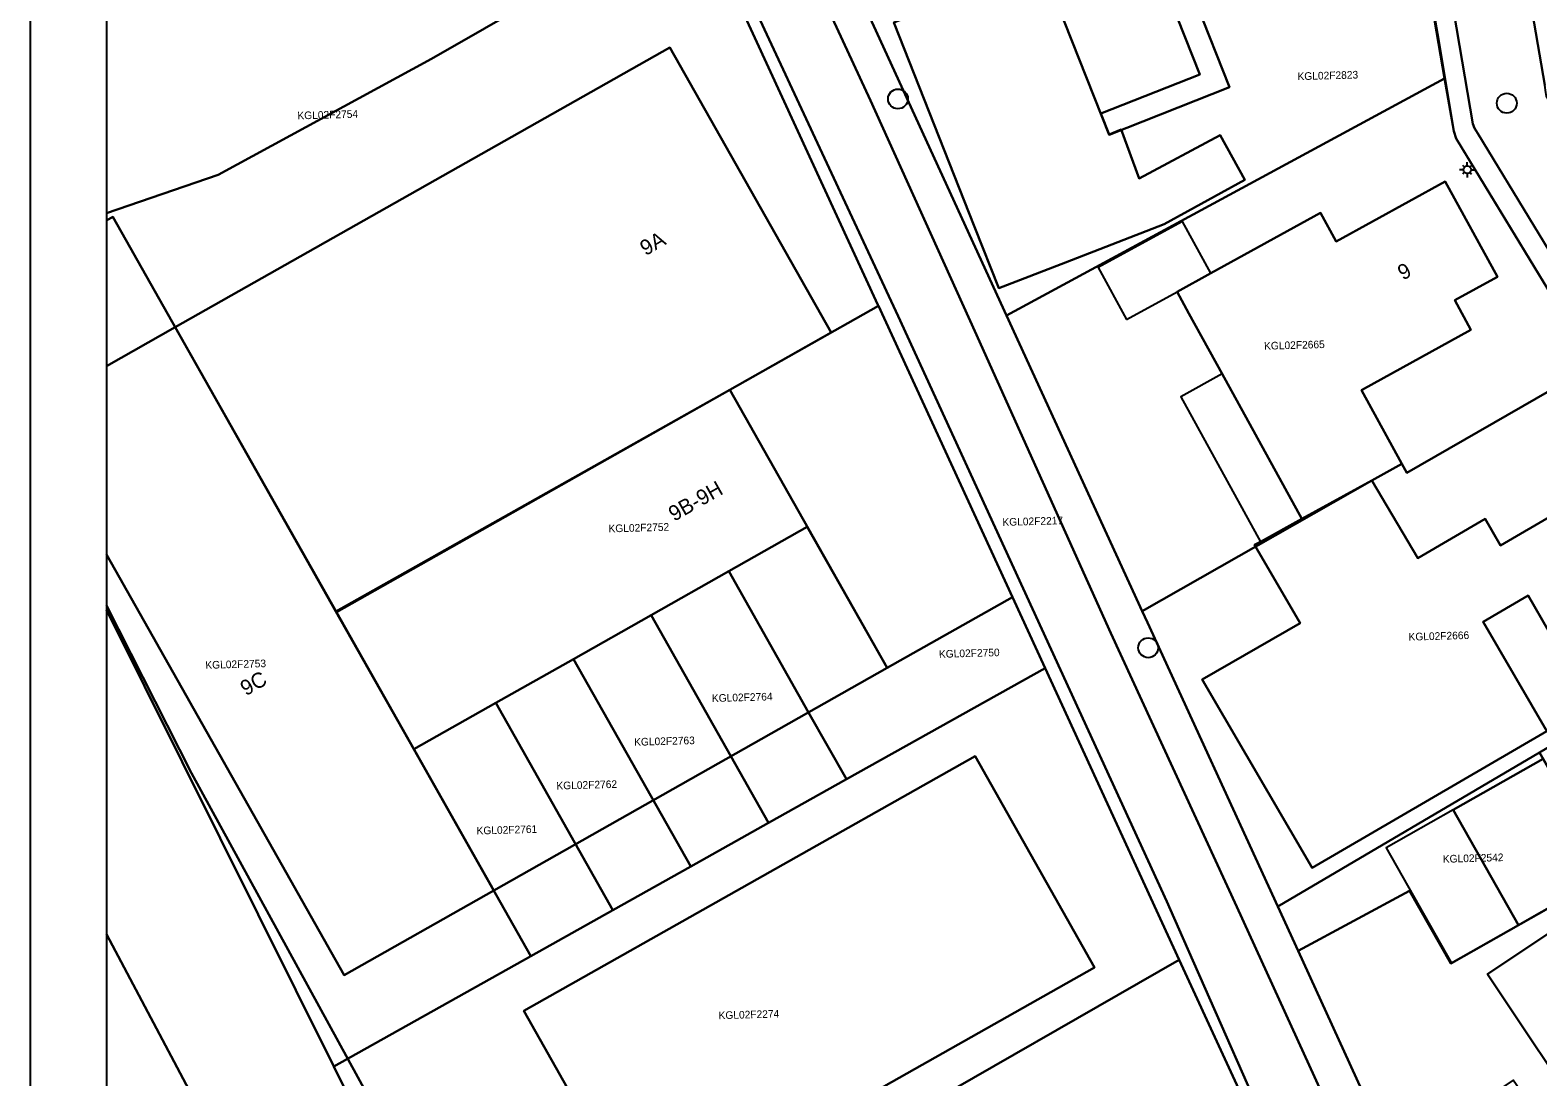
# Model space of a CAD drawing. Extents: x 124901 to 125496, y 515369 to 515789.
# Drawn here: x 124901.4 to 125000.2, y 515576.3 to 515644.9 of the extents above; entities that cross this region are included whole.
import ezdxf

# ---------------------------------------------------------------- set-up
doc = ezdxf.new("R2010")
doc.units = 0
for name, color, linetype in [('Alg Kaders', 7, 'Continuous'), ('Gebouw', 7, 'Continuous'), ('Lichtmast', 7, 'Continuous'), ('Luifel', 7, 'Continuous'), ('Onbegroeid terrein', 7, 'Continuous'), ('Perceelnummers', 7, 'Continuous'), ('Perceelsgrenzen', 7, 'Continuous'), ('Putten', 7, 'Continuous'), ('Teksten', 7, 'Continuous'), ('Vegetatie', 7, 'Continuous'), ('Voetpad', 7, 'Continuous'), ('Water', 7, 'Continuous'), ('Wegen lokale weg', 7, 'Continuous')]:
    doc.layers.add(name, color=color, linetype=linetype)

msp = doc.modelspace()

# ---------------------------------------------------------------- linework, layer by layer
at = {"layer": 'Alg Kaders'}
for points in [[(125495.925, 515789.043), (124901.425, 515789.043), (124901.425, 515368.543), (125495.925, 515368.543)], [(125490.925, 515784.043), (124906.425, 515784.043), (124906.425, 515373.543), (125490.925, 515373.543)]]:
    msp.add_lwpolyline(points, close=True, dxfattribs=at)
at = {"layer": 'Gebouw'}
for points in [[(124973.642, 515653.19), (124967.156, 515650.622), (124967.71, 515649.223), (124958.022, 515645.386), (124963.321, 515632.007), (124964.919, 515627.972), (124969.285, 515629.667), (124975.752, 515632.177), (124981.031, 515635.076), (124979.411, 515638.005), (124974.116, 515635.177), (124972.931, 515638.374), (124972.138, 515638.06), (124971.598, 515639.424), (124978.077, 515641.99)], [(124953.917, 515625.076), (124943.349, 515643.76), (124910.932, 515625.425), (124921.499, 515606.742), (124947.279, 515621.322)], [(124997.585, 515628.727), (124994.154, 515634.97), (124987.009, 515631.045), (124985.984, 515632.91), (124978.805, 515628.965), (124976.59, 515627.748), (124977.37, 515626.328), (124979.548, 515622.364), (124984.768, 515612.863), (124989.352, 515615.381), (124991.328, 515616.467), (124988.669, 515621.306), (124995.85, 515625.251), (124994.785, 515627.188)], [(124947.279, 515621.322), (124921.499, 515606.742), (124931.806, 515588.518), (124957.586, 515603.099)], [(124996.653, 515606.129), (124999.595, 515607.843), (125000.938, 515605.537), (125008.139, 515609.733), (125004.914, 515615.268), (124997.795, 515611.119), (124996.781, 515612.859), (124992.37, 515610.289), (124989.352, 515615.381), (124984.768, 515612.863), (124982.051, 515611.371), (124981.666, 515611.159), (124984.655, 515606.037), (124978.241, 515602.341), (124985.439, 515589.994), (125000.83, 515598.96)], [(124953.656, 515573.582), (124971.175, 515583.466), (124963.357, 515597.324), (124933.784, 515580.64), (124941.602, 515566.782), (124951.601, 515572.423), (124952.463, 515570.923), (124954.442, 515572.183)], [(124998.967, 515586.24), (125000, 515586.825), (125004.862, 515589.576), (125000.585, 515597.133), (124994.69, 515593.797)], [(124996.931, 515583.023), (125000, 515578.448), (125001.346, 515576.442), (125006.281, 515579.753), (125001.865, 515586.334)]]:
    msp.add_lwpolyline(points, close=True, dxfattribs=at)
msp.add_lwpolyline([(124906.425, 515610.538), (124922.012, 515582.979), (124931.806, 515588.518), (124921.499, 515606.742), (124910.932, 515625.425), (124906.425, 515622.876)], dxfattribs=at)
at = {"layer": 'Lichtmast'}
for p, q in [((124995.607, 515636.041), (124995.607, 515636.241)), ((124995.307, 515635.742), (124995.107, 515635.741)), ((124995.395, 515635.529), (124995.323, 515635.458)), ((124995.395, 515635.953), (124995.325, 515636.024)), ((124995.607, 515635.441), (124995.607, 515635.241)), ((124995.819, 515635.953), (124995.89, 515636.025)), ((124995.819, 515635.529), (124995.889, 515635.458)), ((124995.907, 515635.741), (124996.107, 515635.741))]:
    msp.add_line(p, q, dxfattribs=at)
msp.add_circle((124995.607, 515635.741), 0.25, dxfattribs=at)
at = {"layer": 'Luifel'}
for points in [[(124973.283, 515625.931), (124976.59, 515627.748), (124978.805, 515628.965), (124976.939, 515632.36), (124971.418, 515629.327)], [(124982.051, 515611.371), (124984.768, 515612.863), (124979.548, 515622.364), (124976.831, 515620.872)], [(124994.567, 515583.75), (124998.967, 515586.24), (124994.69, 515593.797), (124990.29, 515591.307)]]:
    msp.add_lwpolyline(points, close=True, dxfattribs=at)
at = {"layer": 'Onbegroeid terrein'}
for points in [[(125011.59, 515610.348), (125000, 515629.377), (124996.124, 515635.741), (124994.885, 515637.794), (124994.722, 515638.263), (124993.729, 515644.293), (124989.28, 515669.552)], [(124983.709, 515570.119), (124976.97, 515585.413), (124975.918, 515587.802), (124958.319, 515626.154), (124948.649, 515646.861), (124946.612, 515651.613), (124945.851, 515653.389), (124944.946, 515652.871), (124927.723, 515643.009), (124913.741, 515635.402), (124906.425, 515632.886)], [(124950.358, 515653.544), (124956.491, 515640.283), (124963.337, 515625.163), (124972.256, 515605.38), (124980.497, 515587.44), (124986.865, 515573.529)], [(124906.425, 515622.876), (124910.932, 515625.425), (124943.349, 515643.76), (124953.917, 515625.076), (124947.279, 515621.322), (124957.586, 515603.099), (124931.806, 515588.518), (124922.012, 515582.979), (124906.425, 515610.538)], [(125000.938, 515605.537), (124999.595, 515607.843), (124996.653, 515606.129), (125000.83, 515598.96), (124985.439, 515589.994), (124978.241, 515602.341), (124984.655, 515606.037), (124981.666, 515611.159), (124982.051, 515611.371), (124984.768, 515612.863), (124979.548, 515622.364), (124977.37, 515626.328), (124976.59, 515627.748), (124978.805, 515628.965), (124985.984, 515632.91), (124987.009, 515631.045), (124994.154, 515634.97), (124997.585, 515628.727), (124994.785, 515627.188), (124995.85, 515625.251), (124988.669, 515621.306), (124991.328, 515616.467), (124989.352, 515615.381), (124992.37, 515610.289), (124996.781, 515612.859), (124997.795, 515611.119), (125004.914, 515615.268)], [(124906.425, 515607.187), (124912.007, 515596.198), (124927.338, 515568.172), (124933.584, 515553.409), (124945.808, 515523.755), (124952.343, 515513.489), (124960.185, 515501.344)]]:
    msp.add_lwpolyline(points, dxfattribs=at)
for points in [[(124967.156, 515650.622), (124973.642, 515653.19), (124978.077, 515641.99), (124971.598, 515639.424), (124972.138, 515638.06), (124972.931, 515638.374), (124974.116, 515635.177), (124979.411, 515638.005), (124981.031, 515635.076), (124975.752, 515632.177), (124969.285, 515629.667), (124964.919, 515627.972), (124963.321, 515632.007), (124958.022, 515645.386), (124967.71, 515649.223)], [(124971.175, 515583.466), (124953.656, 515573.582), (124954.442, 515572.183), (124952.463, 515570.923), (124951.601, 515572.423), (124941.602, 515566.782), (124933.784, 515580.64), (124963.357, 515597.324)], [(125000, 515586.825), (124998.967, 515586.24), (124994.69, 515593.797), (125000.585, 515597.133), (125004.862, 515589.576)], [(125000, 515578.448), (124996.931, 515583.023), (125001.865, 515586.334), (125006.281, 515579.753), (125001.346, 515576.442)]]:
    msp.add_lwpolyline(points, close=True, dxfattribs=at)
at = {"layer": 'Perceelsgrenzen'}
for points in [[(125003.919, 515622.943), (124994.885, 515637.794), (124994.722, 515638.263), (124994.121, 515641.709), (124991.381, 515657.67), (124990.821, 515660.932), (124987.929, 515677.777), (124995.814, 515678.943), (124998.603, 515662.333), (125000.264, 515652.44)], [(124906.425, 515665.873), (124928.296, 515674.439), (124932.86, 515675.963), (124932.267, 515677.429), (124938.039, 515676.742), (124938.462, 515670.08), (124938.451, 515669.215), (124939.317, 515665.488), (124939.837, 515664.138), (124956.981, 515626.896), (124957.013, 515626.826), (124947.279, 515621.322), (124921.462, 515606.806), (124906.841, 515632.658), (124906.425, 515632.421)], [(124906.425, 515632.421), (124906.841, 515632.658), (124921.462, 515606.806), (124926.573, 515597.77), (124934.237, 515584.219), (124921.333, 515576.993), (124906.425, 515606.905)], [(124906.425, 515606.905), (124921.333, 515576.993), (124930.943, 515557.71), (124940.501, 515538.532), (124943.739, 515529.107), (124948.774, 515520.44), (124953.675, 515511.607), (124954.973, 515509.339), (124958.344, 515504.072), (124962.674, 515498.659), (124965.419, 515495.246), (124968.664, 515487.719), (124969.251, 515486.357), (124970.049, 515483.901), (124971.604, 515479.591), (124972.78, 515477.748), (124970.518, 515472.925), (124969.575, 515470.638), (124967.68, 515475.755), (124963.455, 515482.582), (124954.711, 515494.572), (124906.425, 515585.657)], [(124906.425, 515585.657), (124954.711, 515494.572)]]:
    msp.add_lwpolyline(points, dxfattribs=at)
for points in [[(124967.939, 515603.092), (124965.798, 515607.743), (124957.013, 515626.826), (124956.981, 515626.896), (124939.837, 515664.138), (124939.317, 515665.488), (124938.451, 515669.215), (124938.462, 515670.08), (124944.847, 515671.033), (124954.658, 515649.647), (124965.42, 515626.188), (124974.304, 515606.823), (124974.642, 515606.086), (124983.184, 515587.466), (124984.517, 515584.561), (124990.215, 515572.14), (124990.831, 515570.832), (124996.668, 515558.434), (124990.606, 515554.681), (124988.558, 515558.301), (124976.736, 515583.981)], [(124966.249, 515652.915), (124972.145, 515638.027), (124980.024, 515641.148), (124977.856, 515646.621), (124977.092, 515646.513), (124975.824, 515655.476), (124991.381, 515657.67), (124994.121, 515641.709), (124965.42, 515626.188), (124954.658, 515649.647)], [(124972.145, 515638.027), (124966.249, 515652.915), (124974.839, 515655.337), (124975.824, 515655.476), (124977.092, 515646.513), (124977.856, 515646.621), (124980.024, 515641.148)], [(125003.919, 515622.943), (124991.65, 515615.879), (124991.328, 515616.467), (124989.352, 515615.381), (124974.304, 515606.823), (124965.42, 515626.188), (124994.121, 515641.709), (124994.722, 515638.263), (124994.885, 515637.794)], [(124952.353, 515612.352), (124947.209, 515609.442), (124942.119, 515606.563), (124937.027, 515603.683), (124931.944, 515600.808), (124926.573, 515597.77), (124921.462, 515606.806), (124947.279, 515621.322), (124957.013, 515626.826), (124965.798, 515607.743), (124957.585, 515603.098)], [(125003.919, 515622.943), (125014.335, 515605.811), (125000.338, 515597.568), (124983.184, 515587.466), (124974.642, 515606.086), (124974.304, 515606.823), (124989.352, 515615.381), (124991.328, 515616.467), (124991.65, 515615.879)], [(124952.441, 515600.189), (124947.209, 515609.442), (124952.353, 515612.352), (124957.585, 515603.098), (124965.798, 515607.743), (124967.939, 515603.092), (124954.921, 515595.802)], [(124952.441, 515600.189), (124954.921, 515595.802), (124949.82, 515592.945), (124942.119, 515606.563), (124947.209, 515609.442)], [(124944.716, 515590.087), (124937.027, 515603.683), (124942.119, 515606.563), (124949.82, 515592.945)], [(125014.335, 515605.811), (125023.679, 515590.367), (125010.774, 515581.584), (124999.882, 515574.212), (124999.285, 515575.095), (124998.619, 515576.08), (124990.831, 515570.832), (124990.215, 515572.14), (124984.517, 515584.561), (124991.834, 515588.499), (124994.531, 515583.73), (125004.862, 515589.576), (125000.338, 515597.568)], [(124937.027, 515603.683), (124944.716, 515590.087), (124939.621, 515587.234), (124931.944, 515600.808)], [(124949.82, 515592.945), (124954.921, 515595.802), (124967.939, 515603.092), (124976.736, 515583.981), (124957.916, 515573.184), (124930.943, 515557.71), (124921.333, 515576.993), (124934.237, 515584.219), (124939.621, 515587.234), (124944.716, 515590.087)], [(124926.573, 515597.77), (124931.944, 515600.808), (124939.621, 515587.234), (124934.237, 515584.219)], [(124983.184, 515587.466), (125000.338, 515597.568), (125004.862, 515589.576), (124994.531, 515583.73), (124991.834, 515588.499), (124984.517, 515584.561)], [(124957.916, 515573.184), (124976.736, 515583.981), (124988.558, 515558.301), (124990.606, 515554.681), (124990.653, 515554.598), (124991.211, 515554.27), (124971.258, 515544.441)]]:
    msp.add_lwpolyline(points, close=True, dxfattribs=at)
at = {"layer": 'Putten'}
for centre in [(124958.3, 515640.38), (124998.2, 515640.1), (124974.7, 515604.42)]:
    msp.add_circle(centre, 0.65, dxfattribs=at)
at = {"layer": 'Vegetatie'}
msp.add_lwpolyline([(124906.425, 515632.886), (124913.741, 515635.402), (124927.723, 515643.009), (124944.946, 515652.871), (124944.324, 515654.312), (124941.151, 515661.401), (124939.61, 515665.134), (124938.494, 515668.878), (124938.055, 515674.312), (124937.715, 515677.01), (124932.136, 515677.601), (124932.198, 515677.278), (124931.939, 515676.391), (124931.216, 515675.361), (124928.652, 515674.059), (124906.425, 515665.361)], dxfattribs=at)
at = {"layer": 'Voetpad'}
for points in [[(124992.256, 515691.049), (124993.89, 515681.429), (124996.221, 515667.71), (125000, 515645.34), (125000.684, 515641.291)], [(125007.429, 515619.839), (125000, 515632.047), (124996.31, 515638.11), (124996.093, 515638.472), (124995.968, 515638.742), (124992.261, 515660.592), (124988.898, 515680.647), (124988.544, 515682.76), (124988.458, 515683.309), (124988.267, 515683.905), (124988.061, 515684.368), (124987.64, 515685.023), (124987.305, 515685.389), (124986.542, 515685.893), (124986.493, 515685.918), (124987.736, 515678.617), (124989.28, 515669.552), (124993.729, 515644.293), (124994.722, 515638.263), (124994.885, 515637.794), (124996.124, 515635.741), (125000, 515629.377), (125011.59, 515610.348)]]:
    msp.add_lwpolyline(points, dxfattribs=at)
at = {"layer": 'Water'}
msp.add_lwpolyline([(124960.185, 515501.344), (124952.343, 515513.489), (124945.808, 515523.755), (124933.584, 515553.409), (124927.338, 515568.172), (124912.007, 515596.198), (124906.425, 515607.187)], dxfattribs=at)
at = {"layer": 'Wegen lokale weg'}
for points in [[(125005.883, 515628.428), (125007.557, 515629.444), (125000.96, 515640.29), (125000.81, 515640.547), (125000.755, 515640.807), (125000.684, 515641.291), (125000, 515645.34), (124996.221, 515667.71), (124993.89, 515681.429), (124988.898, 515680.647), (124992.261, 515660.592), (124995.968, 515638.742), (124996.093, 515638.472), (124996.31, 515638.11), (125000, 515632.047), (125007.429, 515619.839), (125008.7, 515617.743), (125010.315, 515618.724)], [(124986.865, 515573.529), (124980.497, 515587.44), (124972.256, 515605.38), (124963.337, 515625.163), (124956.491, 515640.283), (124950.358, 515653.544)], [(124948.649, 515646.861), (124958.319, 515626.154), (124975.918, 515587.802), (124976.97, 515585.413), (124983.709, 515570.119)]]:
    msp.add_lwpolyline(points, dxfattribs=at)

# ---------------------------------------------------------------- texts
at = {"layer": 'Perceelnummers'}
for s, rotation, p in [('KGL02F2823', 1.62967, (124984.49, 515641.61)), ('KGL02F2754', 1.62891, (124918.947, 515639.039)), ('KGL02F2665', 1.62965, (124982.299, 515623.947)), ('KGL02F2752', 1.62915, (124939.335, 515611.979)), ('KGL02F2217', 1.62945, (124965.151, 515612.402)), ('KGL02F2666', 1.62976, (124991.767, 515604.886)), ('KGL02F2753', 1.62884, (124912.914, 515603.038)), ('KGL02F2750', 1.6294, (124960.992, 515603.758)), ('KGL02F2764', 1.62922, (124946.111, 515600.865)), ('KGL02F2763', 1.62916, (124941.015, 515597.996)), ('KGL02F2762', 1.62911, (124935.921, 515595.129)), ('KGL02F2761', 1.62904, (124930.688, 515592.183)), ('KGL02F2542', 1.62979, (124994.013, 515590.33)), ('KGL02F2274', 1.62923, (124946.549, 515580.082))]:
    msp.add_text(s, height=0.5, rotation=rotation, dxfattribs=at).set_placement(p)
at = {"layer": 'Teksten'}
for s, rotation, p in [('9A', 29.5, (124941.756, 515630.078)), ('9', 28.8, (124991.396, 515628.473)), ('9B-9H', 29.5, (124943.625, 515612.671)), ('9C', 29.5, (124915.562, 515601.239))]:
    msp.add_text(s, height=1, rotation=rotation, dxfattribs=at).set_placement(p)

doc.saveas('drawing.dxf')
